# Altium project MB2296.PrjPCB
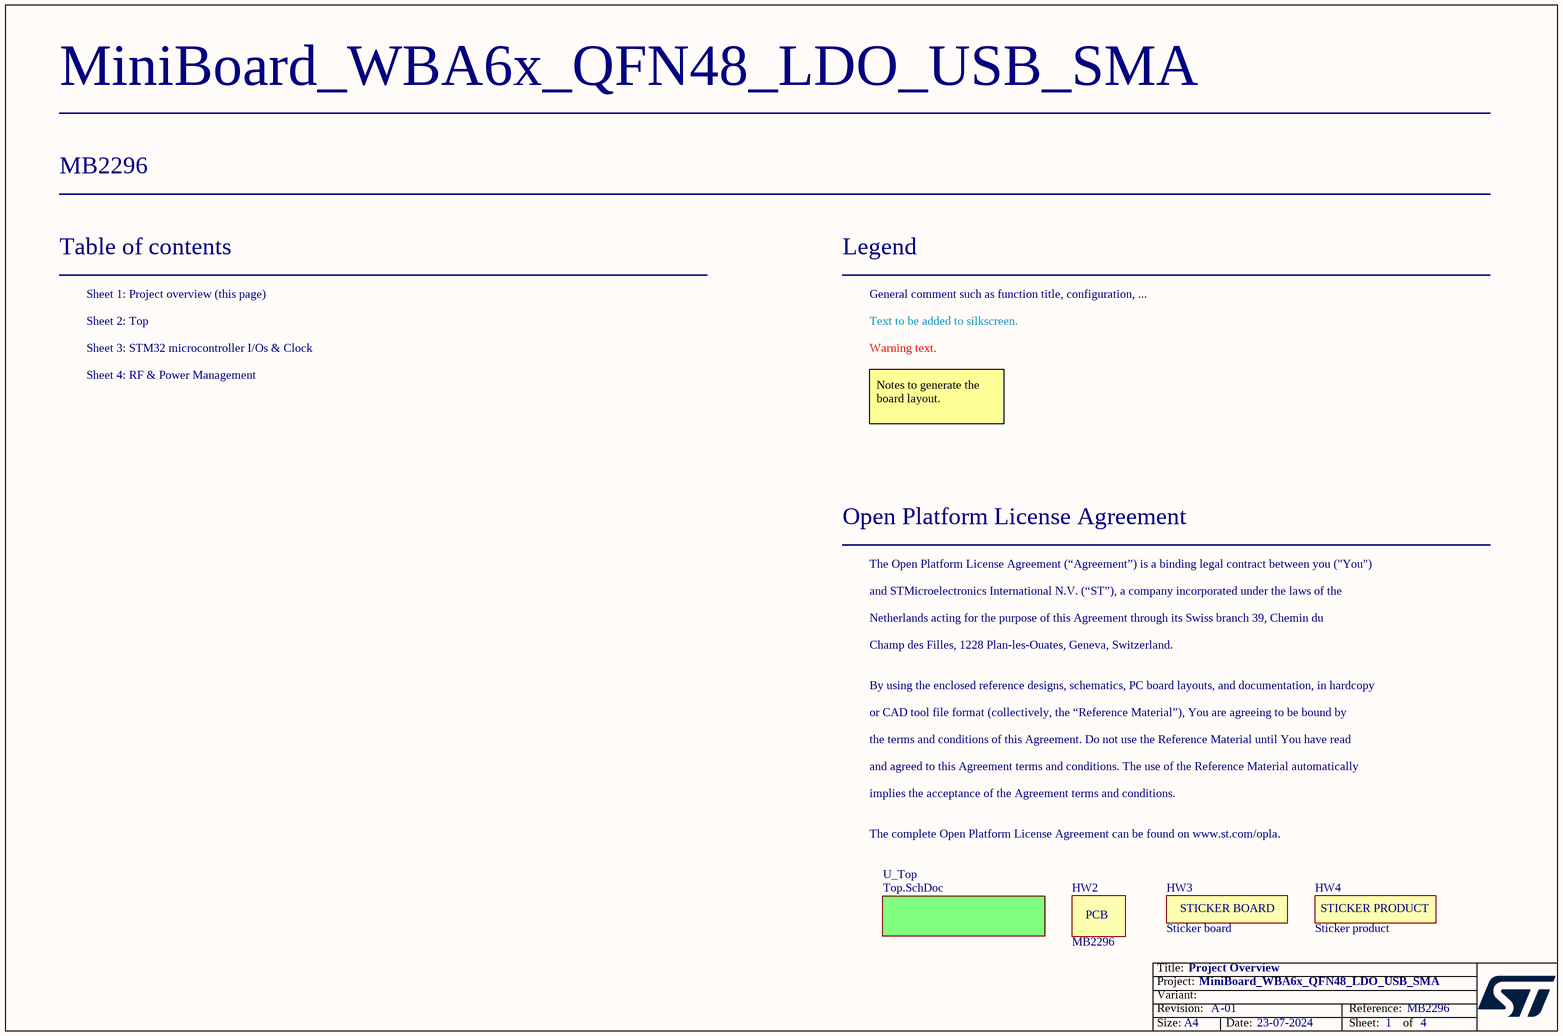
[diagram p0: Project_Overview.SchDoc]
Board_Assembly_Revision: 01; Board_Document_Date: 23-07-2024; Board_Name: MiniBoard_WBA6x_QFN48_LDO_USB_SMA; Board_PCB_Revision: A; Board_Reference: MB2296
4 sheets, 92 parts. Net scope: flat (ports and power ports of the same name join across sheets).
Board file: MB2296.PcbDoc
Sheets:
  Project_Overview.SchDoc
    U_Top = Top.SchDoc
      STM32 microcontroller I/Os & Clock = MCU.SchDoc
      RF & Power Management Schematic = RF&Power_Management.SchDoc

## Sheet Project_Overview.SchDoc: Project Overview
size A4; Date: Not used; ApprovedBy: Not used; CheckedBy: Not used; Author: Not used; CompanyName: STMicroelectronics; DrawnBy: Not used; Engineer: Not used; Organization: Not used; Address1: Not used; Address2: Not used; Address3: Not used; Address4: Not used; DocumentNumber: 1; Revision: Not used; SheetNumber: 1; SheetTotal: 4

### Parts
HW2  value MB2296  (hidden comment: PCB)  (no BOM)
HW3  value Sticker board  [STICKER_BOARD_25X5]  (hidden comment: STICKER_BOARD)  (no BOM)
HW4  value Sticker product  [STICKER_PRODUCT_25X5]  (hidden comment: STICKER_PRODUCT)  (no BOM)

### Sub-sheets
U_Top = Top.SchDoc: no entries

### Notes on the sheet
- Table of contents
- Sheet 1: Project overview (this page)
- Legend
- General comment such as function title, configuration, ...
- Sheet 2: Top
- Sheet 3: STM32 microcontroller I/Os & Clock
- Sheet 4: RF & Power Management
- Text to be added to silkscreen.
- Warning text.
- Notes to generate the board layout.
- Open Platform License Agreement
- The Open Platform License Agreement (“Agreement”) is a binding legal contract between you ("You")
- and STMicroelectronics International N.V. (“ST”), a company incorporated under the laws of the
- Netherlands acting for the purpose of this Agreement through its Swiss branch 39, Chemin du
- Champ des Filles, 1228 Plan-les-Ouates, Geneva, Switzerland.
- By using the enclosed reference designs, schematics, PC board layouts, and documentation, in hardcopy
- or CAD tool file format (collectively, the “Reference Material”), You are agreeing to be bound by
- the terms and conditions of this Agreement. Do not use the Reference Material until You have read
- and agreed to this Agreement terms and conditions. The use of the Reference Material automatically
- implies the acceptance of the Agreement terms and conditions.
- The complete Open Platform License Agreement can be found on www.st.com/opla.

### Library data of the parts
HW2 = MCD-03003: PCB MB1805, 4L2S of MiniBoard for STM32WBA55, QFN48, SMPS, SMA.; Part_Preference: Recommended; Manufacturer: PLOTEC; ShowFields: YES; ID: 5119
HW3 = MCD-02190: Sticker board 25x5 mm; Part_Type: Misc; Part_Preference: Recommended
HW4 = MCD-02189: Sticker product 25x5 mm; Part_Type: Misc; Part_Preference: Recommended

## Sheet Top.SchDoc: Top Schematic
size A4; Date: Not used; ApprovedBy: Not used; CheckedBy: Not used; Author: Not used; CompanyName: STMicroelectronics; DrawnBy: Not used; Engineer: Not used; Organization: Not used; Address1: Not used; Address2: Not used; Address3: Not used; Address4: Not used; DocumentNumber: 2; Revision: Not used; SheetNumber: 2; SheetTotal: 4
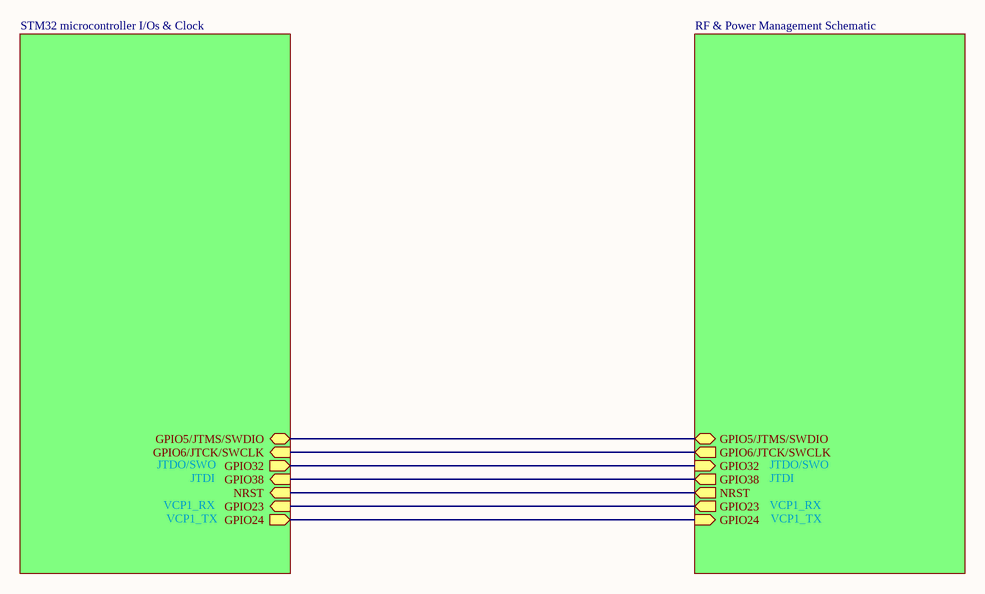
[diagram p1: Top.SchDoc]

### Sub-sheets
RF & Power Management Schematic = RF&Power_Management.SchDoc: GPIO5/JTMS/SWDIO (bidir), GPIO6/JTCK/SWCLK (out), GPIO32 (in), GPIO38 (out), NRST (out), GPIO23 (out), GPIO24 (in)
STM32 microcontroller I/Os & Clock = MCU.SchDoc: GPIO5/JTMS/SWDIO (bidir), GPIO6/JTCK/SWCLK (in), GPIO32 (out), GPIO38 (in), NRST (in), GPIO23 (in), GPIO24 (out)

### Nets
(unnamed): sheet STM32 microcontroller I/Os & Clock/GPIO5/JTMS/SWDIO, sheet RF & Power Management Schematic/GPIO5/JTMS/SWDIO
(unnamed): sheet STM32 microcontroller I/Os & Clock/GPIO6/JTCK/SWCLK, sheet RF & Power Management Schematic/GPIO6/JTCK/SWCLK  [a separate net that carries the same name]
(unnamed): sheet STM32 microcontroller I/Os & Clock/GPIO32, sheet RF & Power Management Schematic/GPIO32  [a separate net that carries the same name]
(unnamed): sheet STM32 microcontroller I/Os & Clock/GPIO38, sheet RF & Power Management Schematic/GPIO38  [a separate net that carries the same name]
(unnamed): sheet STM32 microcontroller I/Os & Clock/NRST, sheet RF & Power Management Schematic/NRST  [a separate net that carries the same name]
(unnamed): sheet STM32 microcontroller I/Os & Clock/GPIO23, sheet RF & Power Management Schematic/GPIO23  [a separate net that carries the same name]
(unnamed): sheet STM32 microcontroller I/Os & Clock/GPIO24, sheet RF & Power Management Schematic/GPIO24  [a separate net that carries the same name]

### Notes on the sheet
- JTDO/SWO
- VCP1_RX
- VCP1_TX
- JTDI

## Sheet MCU.SchDoc: STM32 microcontroller I/Os & Clock
size A4; Date: Not used; ApprovedBy: Not used; CheckedBy: Not used; Author: Not used; CompanyName: STMicroelectronics; DrawnBy: Not used; Engineer: Not used; Organization: Not used; Address1: Not used; Address2: Not used; Address3: Not used; Address4: Not used; DocumentNumber: 3; Revision: Not used; SheetNumber: 3; SheetTotal: 4
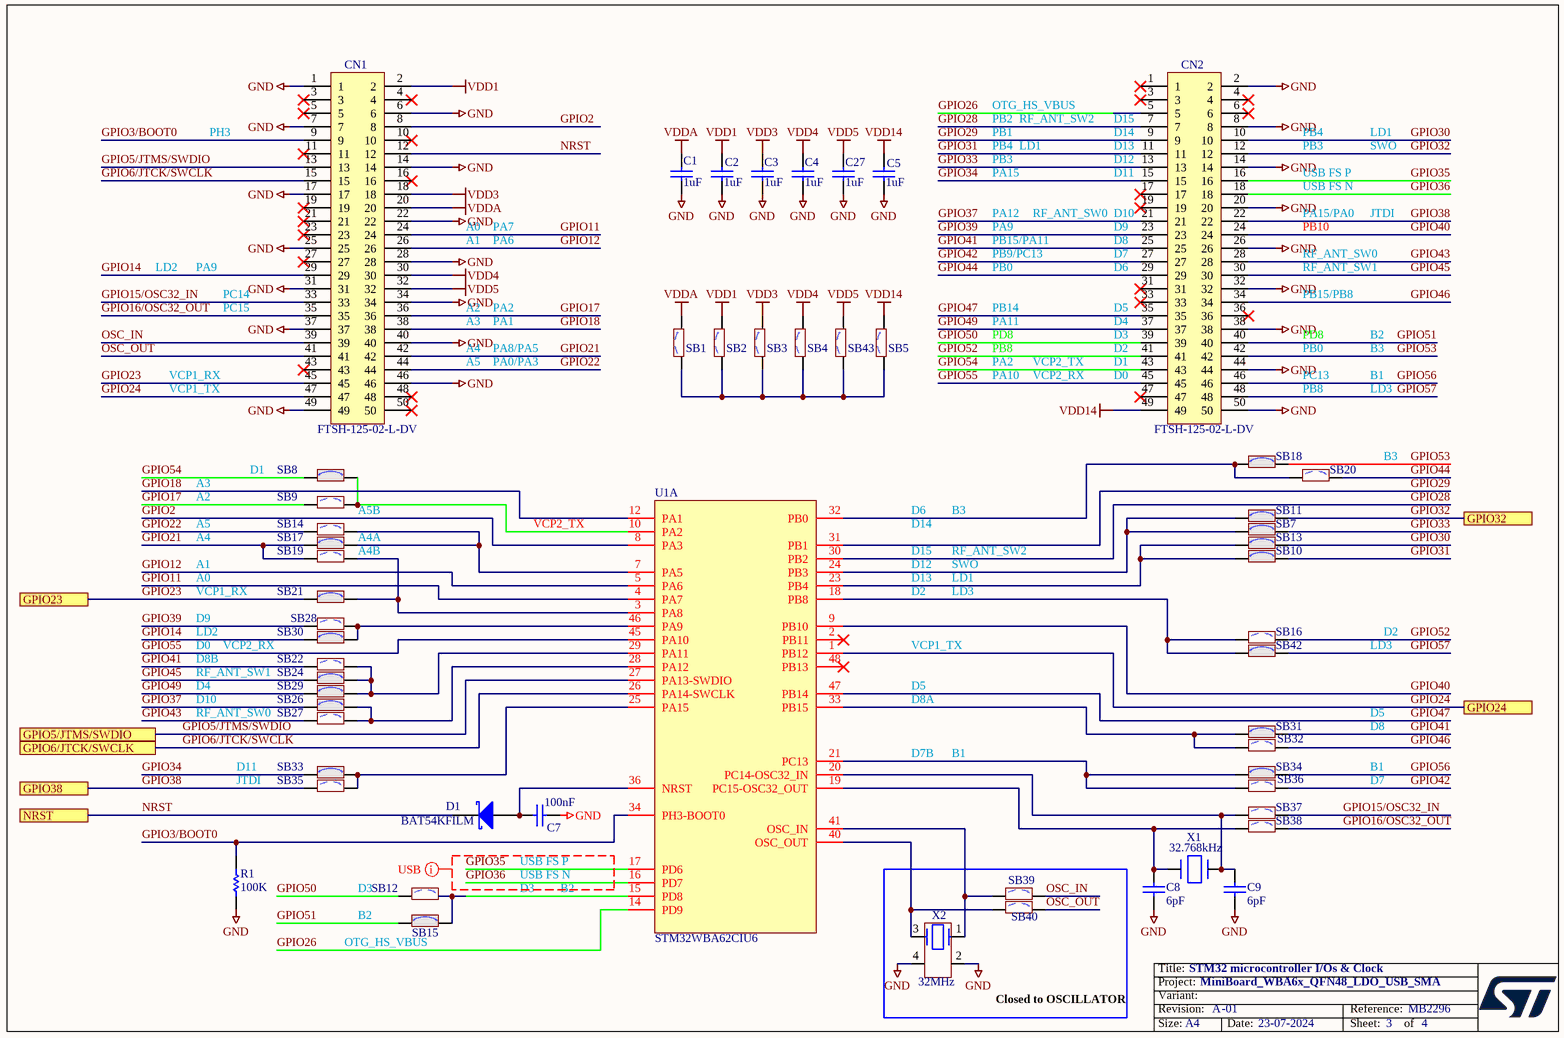
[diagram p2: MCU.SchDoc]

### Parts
C1  value 1uF  [C0402]  (hidden comment: Capacitor)
C2  value 1uF  [C0402]  (hidden comment: Capacitor)
C3  value 1uF  [C0402]  (hidden comment: Capacitor)
C4  value 1uF  [C0402]  (hidden comment: Capacitor)
C5  value 1uF  [C0402]  (hidden comment: Capacitor)
C7  value 100nF  [C0402]  (hidden comment: Capacitor)
C8  value 6pF  [C0402]  (hidden comment: Capacitor)
C9  value 6pF  [C0402]  (hidden comment: Capacitor)
C27  value 1uF  [C0402]  (hidden comment: Capacitor)
CN1  FTSH-125-02-L-DV  [CON_SAMTEC_FTSH-125-02-L-DV]
CN2  FTSH-125-02-L-DV  [CON_SAMTEC_FTSH-125-02-L-DV]
D1  value BAT54KFILM  [DIO_SOD523_1A_2K]  (hidden comment: SCHOTTKY_1A_2K)
R1  value 100K  [R0402]  (hidden comment: Resistor)
SB1  SB_OFF  [SOLDER-BRIDGE_R0402-0R]  (value not drawn)
SB2  SB_OFF  [SOLDER-BRIDGE_R0402-0R]  (value not drawn)
SB3  SB_OFF  [SOLDER-BRIDGE_R0402-0R]  (value not drawn)
SB4  SB_OFF  [SOLDER-BRIDGE_R0402-0R]  (value not drawn)
SB5  SB_OFF  [SOLDER-BRIDGE_R0402-0R]  (value not drawn)
SB7  SB_ON  [SOLDER-BRIDGE_R0402-0R]  (value not drawn)
SB8  SB_ON  [SOLDER-BRIDGE_R0402-0R]  (value not drawn)
SB9  SB_OFF  [SOLDER-BRIDGE_R0402-0R]  (value not drawn)
SB10  SB_ON  [SOLDER-BRIDGE_R0402-0R]  (value not drawn)
SB11  SB_ON  [SOLDER-BRIDGE_R0402-0R]  (value not drawn)
SB12  SB_OFF  [SOLDER-BRIDGE_R0402-0R]  (value not drawn)
SB13  SB_ON  [SOLDER-BRIDGE_R0402-0R]  (value not drawn)
SB14  SB_OFF  [SOLDER-BRIDGE_R0402-0R]  (value not drawn)
SB15  SB_ON  [SOLDER-BRIDGE_R0402-0R]  (value not drawn)
SB16  SB_OFF  [SOLDER-BRIDGE_R0402-0R]  (value not drawn)
SB17  SB_ON  [SOLDER-BRIDGE_R0402-0R]  (value not drawn)
SB18  SB_ON  [SOLDER-BRIDGE_R0402-0R]  (value not drawn)
SB19  SB_OFF  [SOLDER-BRIDGE_R0402-0R]  (value not drawn)
SB20  SB_OFF  [SOLDER-BRIDGE_R0402-0R]  (value not drawn)
SB21  SB_ON  [SOLDER-BRIDGE_R0402-0R]  (value not drawn)
SB22  SB_OFF  [SOLDER-BRIDGE_R0402-0R]  (value not drawn)
SB24  SB_ON  [SOLDER-BRIDGE_R0402-0R]  (value not drawn)
SB26  SB_ON  [SOLDER-BRIDGE_R0402-0R]  (value not drawn)
SB27  SB_OFF  [SOLDER-BRIDGE_R0402-0R]  (value not drawn)
SB28  SB_OFF  [SOLDER-BRIDGE_R0402-0R]  (value not drawn)
SB29  SB_ON  [SOLDER-BRIDGE_R0402-0R]  (value not drawn)
SB30  SB_ON  [SOLDER-BRIDGE_R0402-0R]  (value not drawn)
SB31  SB_ON  [SOLDER-BRIDGE_R0402-0R]  (value not drawn)
SB32  SB_OFF  [SOLDER-BRIDGE_R0402-0R]  (value not drawn)
SB33  SB_ON  [SOLDER-BRIDGE_R0402-0R]  (value not drawn)
SB34  SB_ON  [SOLDER-BRIDGE_R0402-0R]  (value not drawn)
SB35  SB_OFF  [SOLDER-BRIDGE_R0402-0R]  (value not drawn)
SB36  SB_OFF  [SOLDER-BRIDGE_R0402-0R]  (value not drawn)
SB37  SB_OFF  [SOLDER-BRIDGE_R0402-0R]  (value not drawn)
SB38  SB_OFF  [SOLDER-BRIDGE_R0402-0R]  (value not drawn)
SB39  SB_OFF  [SOLDER-BRIDGE_R0402-0R]  (value not drawn)
SB40  SB_OFF  [SOLDER-BRIDGE_R0402-0R]  (value not drawn)
SB42  SB_ON  [SOLDER-BRIDGE_R0402-0R]  (value not drawn)
SB43  SB_OFF  [SOLDER-BRIDGE_R0402-0R]  (value not drawn)
U1  STM32WBA62CIU6  [STM32WB62CGU6]  (part A of 3)
X1  value 32.768kHz  [CRY_NX1610SE_2P]  (hidden comment: XTAL_2_PINS)
X2  value 32MHz  [CRY_NX1612SA_4P]  (hidden comment: XTAL_4_PINS)

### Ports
GPIO5/JTMS/SWDIO, GPIO6/JTCK/SWCLK, GPIO23, GPIO24, GPIO32, GPIO38, NRST

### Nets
GND: C1.1 C2.1 C3.1 C4.1 C5.1 C7.1 C8.1 C9.1 C27.1 CN1.1 CN1.6 CN1.7 CN1.14 CN1.17 CN1.22 CN1.25 CN1.28 CN1.31 CN1.34 CN1.37 CN1.40 CN1.46 CN1.49 CN2.2 CN2.8 CN2.14 CN2.20 CN2.26 CN2.32 CN2.38 CN2.44 CN2.50 R1.2 X2.2 X2.4
VDD1: C2.2 CN1.2 SB2.2
VDD3: C3.2 CN1.18 SB3.2
VDD4: C4.2 CN1.30 SB4.2
VDD5: C27.2 CN1.32 SB43.2
VDD14: C5.2 CN2.49 SB5.2
VDDA: C1.2 CN1.20 SB1.2
GPIO2: CN1.8 U1.8(PA3)
GPIO3/BOOT0: CN1.9 R1.1 U1.34(PH3-BOOT0)
GPIO5/JTMS/SWDIO: CN1.13 U1.27(PA13-SWDIO) ; port GPIO5/JTMS/SWDIO
GPIO6/JTCK/SWCLK: CN1.15 U1.26(PA14-SWCLK) ; port GPIO6/JTCK/SWCLK
GPIO11: CN1.24 U1.4(PA7)
GPIO12: CN1.26 U1.5(PA6)
GPIO14: CN1.29 SB30.1
GPIO15/OSC32_IN: CN1.33 SB37.2
GPIO16/OSC32_OUT: CN1.35 SB38.2
GPIO17: CN1.36 SB9.1
GPIO18: CN1.38 U1.12(PA1)
GPIO21: CN1.42 SB17.1 SB19.1
GPIO22: CN1.44 SB14.1
GPIO23: CN1.45 SB21.1 ; port GPIO23
GPIO24: CN1.47 U1.1(PB12) ; port GPIO24
GPIO26: CN2.5 U1.14(PD9)
GPIO28: CN2.7 U1.30(PB2)
GPIO29: CN2.9 U1.31(PB1)
GPIO30: CN2.10 SB13.2
GPIO31: CN2.11 SB10.2
GPIO32: CN2.12 SB11.2 ; port GPIO32
GPIO33: CN2.13 SB7.2
GPIO34: CN2.15 SB33.1
GPIO35: CN2.16 U1.17(PD6)
GPIO36: CN2.18 U1.16(PD7)
GPIO37: CN2.21 SB26.1
GPIO38: CN2.22 SB35.1 ; port GPIO38
GPIO39: CN2.23 SB28.1
GPIO40: CN2.24 U1.9(PB10)
GPIO41: CN2.25 SB22.1 SB31.2
GPIO42: CN2.27 SB36.2
GPIO43: CN2.28 SB27.1
GPIO44: CN2.29 SB20.2
GPIO45: CN2.30 SB24.1
GPIO46: CN2.34 SB32.2
GPIO47: CN2.35 U1.47(PB14)
GPIO49: CN2.37 SB29.1
GPIO50: CN2.39 SB12.1
GPIO51: CN2.40 SB15.2
GPIO52: CN2.41 SB16.2
GPIO53: CN2.42 SB18.2
GPIO54: CN2.43 SB8.1
GPIO55: CN2.45 U1.45(PA10)
GPIO56: CN2.46 SB34.2
GPIO57: CN2.48 SB42.2
NRST: CN1.12 D1.2(K) ; port NRST
OSC_IN: CN1.39 SB39.2
OSC_OUT: CN1.41 SB40.2
NetC7_2: C7.2 D1.1(A) U1.36(NRST)
NetC8_2: C8.2 SB38.1 U1.19(PC15-OSC32_OUT) X1.2(X2)
NetC9_2: C9.2 SB37.1 U1.20(PC14-OSC32_IN) X1.1(X1)
NetSB1_1: SB1.1 SB2.1 SB3.1 SB4.1 SB5.1 SB43.1
NetSB7_1: SB7.1 SB11.1 U1.24(PB3)
NetSB8_2: SB8.2 SB9.2 U1.10(PA2)
NetSB10_1: SB10.1 SB13.1 U1.23(PB4)
NetSB12_2: SB12.2 SB15.1 U1.15(PD8)
NetSB14_2: SB14.2 SB17.2 U1.7(PA5)
NetSB16_1: SB16.1 SB42.1 U1.18(PB8)
NetSB18_1: SB18.1 SB20.1 U1.32(PB0)
NetSB19_2: SB19.2 SB21.2 U1.3(PA8)
NetSB22_2: SB22.2 SB24.2 SB29.2 U1.29(PA11)
NetSB26_2: SB26.2 SB27.2 U1.28(PA12)
NetSB28_2: SB28.2 SB30.2 U1.46(PA9)
NetSB31_1: SB31.1 SB32.1 U1.33(PB15)
NetSB33_2: SB33.2 SB35.2 U1.25(PA15)
NetSB34_1: SB34.1 SB36.1 U1.21(PC13)
NetSB39_1: SB39.1 U1.41(OSC_IN) X2.1
NetSB40_1: SB40.1 U1.40(OSC_OUT) X2.3

Not connected (* = marked no-connect by the designer): CN1 3* 4* 5* 10* 11* 16* 19* 21* 23* 27* 43* 48* 50*; CN2 1* 3* 4* 6* 17* 19* 31* 33* 36* 47*; U1 2(PB11)* 48(PB13)*

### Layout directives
rule Undefined; rule Matched Net Lengths [Tolerance = 2mm]; rule Impedance Constraint [Min = 85.00    Max = 95.00    ]: GPIO35, GPIO36

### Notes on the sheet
- OTG_HS_VBUS
- PH3
- PB1
- PB2
- PB3
- PB4
- PA15
- LD1
- RF_ANT_SW2
- (near CN2) D11
- (near CN2) D13
- (near CN2) D14
- (near CN2) D15
- (near CN2) D12
- USB FS P
- SWO
- A0
- A1
- PA6
- PA7
- PA9
- PB15/PA11
- PA12
- RF_ANT_SW0
- (near CN2) D10
- (near CN2) D9
- (near CN2) D8
- PA15/PA0
- PB10
- USB FS N
- JTDI
- LD2
- PC14
- PC15
- A2
- PA2
- PB14
- PB0
- PB9/PC13
- (near CN2) D7
- (near CN2) D6
- (near CN2) D5
- RF_ANT_SW1
- PB15/PB8
- VCP1_RX
- A5
- A4
- A3
- PA0/PA3
- PA8/PA5
- PA1
- PA11
- PA10
- PD8
- PB8
- VCP2_TX
- VCP2_RX
- (near CN2) D1
- (near CN2) D4
- (near CN2) D3
- (near CN2) D2
- (near CN2) D0
- PC13
- B1
- B2
- B3
- VCP1_TX
- LD3
- D1
- A5B
- D6
- A4B
- A4A
- D12
- D13
- D15
- D14
- D0
- D9
- D2
- D10
- D8B
- D4
- D8A
- D5
- D11
- D7B
- D7
- D8
- D3
- (near SB15) OTG_HS_VBUS
- Closed to OSCILLATOR

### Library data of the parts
C1-C5 C27 = MCD-01722: Capacitor, MLCC, 1uF, 10V, X5R, +/-10%, 0402, T=0.5mm; Part_Preference: Recommended; Manufacturer: YAGEO; Manufacturer_Part_Number: CC0402KRX5R6BB105; Component_Country_Of_Origin: China
C7 = MCD-00006: Capacitor, MLCC, 100nF, 16V, X7R, +/-10%, 0402, T=0.5mm; Manufacturer_Part_Number: CC0402KRX7R7BB104; Manufacturer: YAGEO; Alternate_Manufacturer_Part_Number: GCM155R71C104KA55D; Alternate_Manufacturer: MURATA; Part_Preference: Recommended; Order_Code_RS: 616-9701
C8 C9 = MCD-03185: Capacitor, MLCC, 6 pF, 50V, NPO, ±0,25pF, 0402, T=0.5mm; Part_Preference: Recommended; Manufacturer: MURATA; Manufacturer_Part_Number: GJM1555C1H6R0CB01; Order_Code_RS: 170-6040; ShowFields: YES; ID: 5301
CN1 CN2 = MCD-02746: Header, 25x2, 12.7mm, VR, SMD, T=4.83mm; Part_Type: Connector; Part_Preference: Recommended; Manufacturer: SAMTEC; Value: Header 25x2; ShowFields: YES; ID: 4858; Component_Country_Of_Origin: China, Costa Rica, Malaysia, USA, Vietnam
D1 = MCD-01677: Small signal Schottky diodes; Part_Type: Diode; Manufacturer: STMICROELECTRONICS; BMS_Part_Number: 9151123; Part_Preference: Recommended; Manufacturer_HQ_COO: EU
R1 = MCD-00059: Resistor, 100K, 0402, +/-1%, 1/16W; Part_Preference: Recommended; Manufacturer: YAGEO; Manufacturer_Part_Number: RC0402FR-07100KL; Component_Country_Of_Origin: China
SB1-SB5 SB9 SB12 SB14 SB16 SB19 SB20 SB22 SB27 SB28 SB32 SB35-SB40 SB43 = MCD-02162: Solder Bridge 0402 OFF; Part_Type: Misc; Part_Preference: Recommended; Manufacturer: YAGEO; Manufacturer_Part_Number: RC0402JR-070RL; Order_Code_RS: 618-5804; Component_Country_Of_Origin: China
SB7 SB8 SB10 SB11 SB13 SB15 SB17 SB18 SB21 SB24 SB26 SB29-SB31 SB33 SB34 SB42 = MCD-01618: Solder Bridge 0402 ON; Part_Type: Misc; Part_Preference: Recommended; Manufacturer: YAGEO; Manufacturer_Part_Number: RC0402JR-070RL; Order_Code_RS: 618-5804; Component_Country_Of_Origin: China
U1 = STM32WBA62CIU6: STM32WBA62CIU6 QFN48_USB_LDO; Internal_Part_Number: MCD-04241; Manufacturer: STmicroelectronics; ECCN_EU: NEC°°°; ECCN_US: EAR99°°°
X1 = MCD-02579: Crystal, 32.768kHz, 6pF, +/-20ppm, 70KR, 1.6x1mm; Part_Type: Crystal_Osc; Part_Preference: Recommended; Manufacturer: NDK; Manufacturer_Part_Number: NX1610SE-32.768KHZ-EXS00A-MU01501
X2 = MCD-02578: Crystal, 32MHz, 8pF, +/-10ppm, 40R, 1612(metric), T=0.3mm; Part_Type: Crystal_Osc; Part_Preference: Recommended; Manufacturer: NDK; Manufacturer_Part_Number: NX1612SA-32MHZ-EXS00A-CS09166

## Sheet RF&Power_Management.SchDoc: RF & Power Management Schematic
size A4; Date: Not used; ApprovedBy: Not used; CheckedBy: Not used; Author: Not used; CompanyName: STMicroelectronics; DrawnBy: Not used; Engineer: Not used; Organization: Not used; Address1: Not used; Address2: Not used; Address3: Not used; Address4: Not used; DocumentNumber: 4; Revision: Not used; SheetNumber: 4; SheetTotal: 4
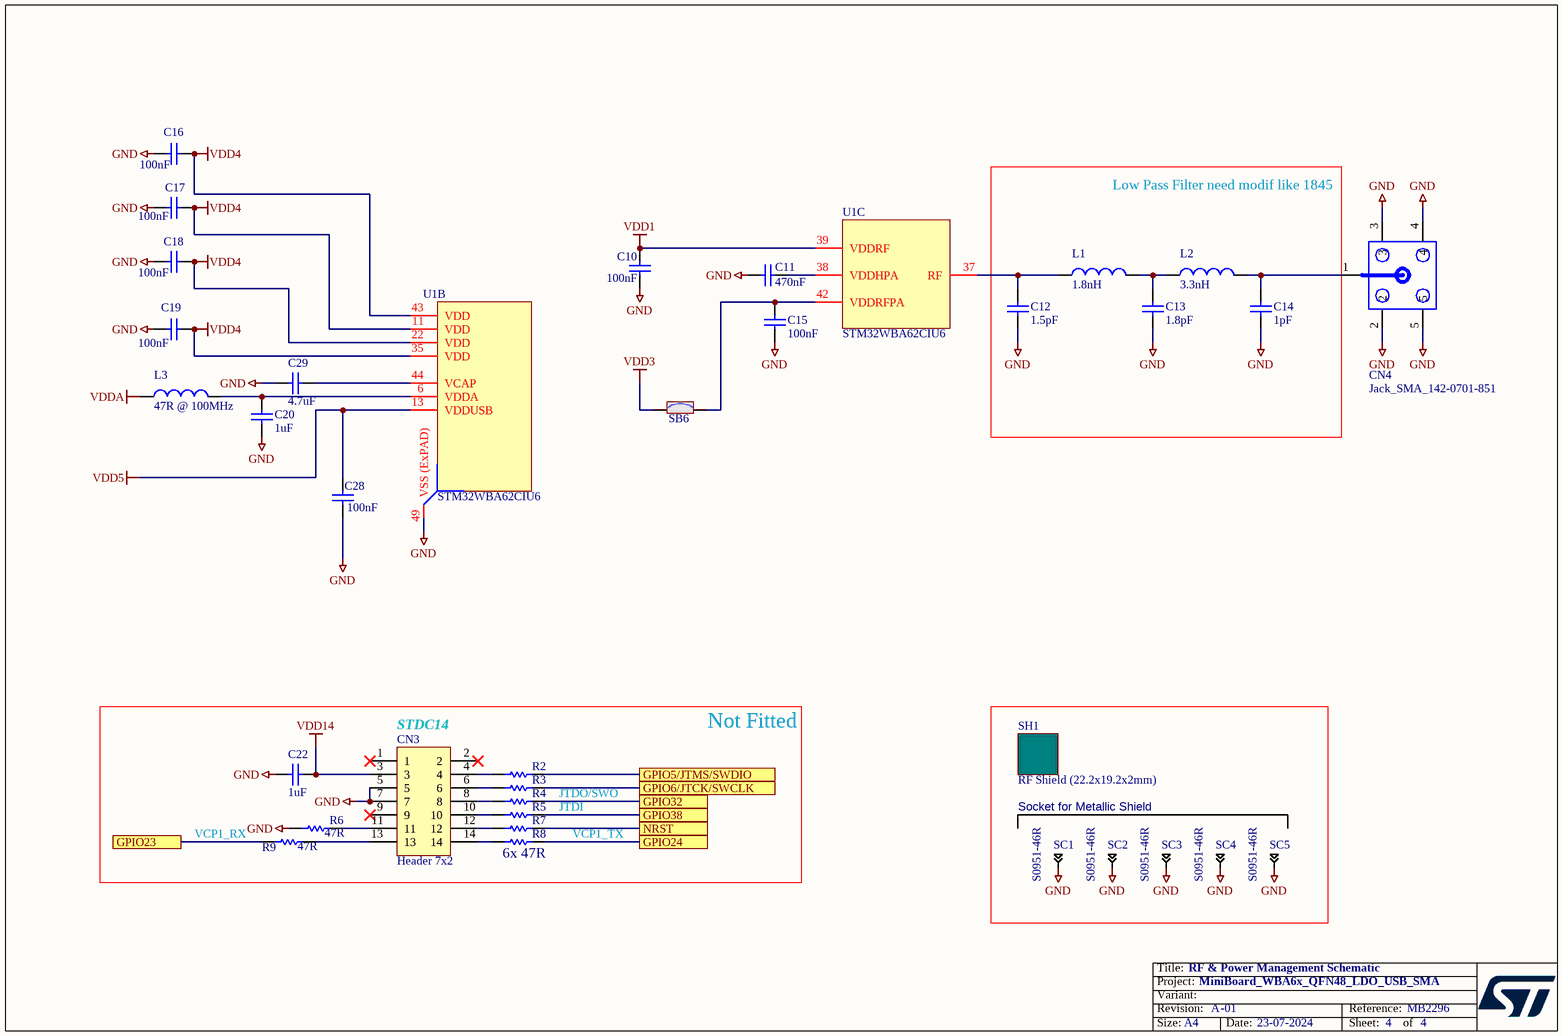
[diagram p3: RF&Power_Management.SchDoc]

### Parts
C10  value 100nF  [C0402]  (hidden comment: Capacitor)
C11  value 470nF  [C0603]  (hidden comment: Capacitor)
C12  value 1.5pF  [C0402]  (hidden comment: Capacitor)
C13  value 1.8pF  [C0402]  (hidden comment: Capacitor)
C14  value 1pF  [C0402_MURATA_GRM155_H0P5]  (hidden comment: Capacitor)
C15  value 100nF  [C0402]  (hidden comment: Capacitor)
C16  value 100nF  [C0402]  (hidden comment: Capacitor)
C17  value 100nF  [C0402]  (hidden comment: Capacitor)
C18  value 100nF  [C0402]  (hidden comment: Capacitor)
C19  value 100nF  [C0402]  (hidden comment: Capacitor)
C20  value 1uF  [C0402]  (hidden comment: Capacitor)
C22  value 1uF  [C0603]  (hidden comment: Capacitor)
C28  value 100nF  [C0402]  (hidden comment: Capacitor)
C29  value 4.7uF  [C0603_H0P8]  (hidden comment: Capacitor)
CN3  Header 7x2  [CON_SAMTEC_FTSH-107-01-L-DV-K-A]
CN4  value Jack_SMA_142-0701-851  [CON_SMA-RF_CINCH_142-0701-851]  (hidden comment: mmcx)
L1  value 1.8nH  [C0402]  (hidden comment: Inductor)
L2  value 3.3nH  [C0402]  (hidden comment: Inductor)
L3  value 47R @ 100MHz  [IND_0603_H0P8]  (hidden comment: Inductor)
R2  Resistor  [R0402]  (value not drawn)
R3  Resistor  [R0402]  (value not drawn)
R4  Resistor  [R0402]  (value not drawn)
R5  Resistor  [R0402]  (value not drawn)
R6  value 47R  [R0402]  (hidden comment: Resistor)
R7  Resistor  [R0402]  (value not drawn)
R8  Resistor  [R0402]  (value not drawn)
R9  value 47R  [R0402]  (hidden comment: Resistor)
SB6  SB_ON  [SOLDER-BRIDGE_R0402-0R]  (value not drawn)
SC1  value S0951-46R  [CLIP_HARWIN_S0951-46R]  (hidden comment: Shield-clip_S0951-46R)
SC2  value S0951-46R  [CLIP_HARWIN_S0951-46R]  (hidden comment: Shield-clip_S0951-46R)
SC3  value S0951-46R  [CLIP_HARWIN_S0951-46R]  (hidden comment: Shield-clip_S0951-46R)
SC4  value S0951-46R  [CLIP_HARWIN_S0951-46R]  (hidden comment: Shield-clip_S0951-46R)
SC5  value S0951-46R  [CLIP_HARWIN_S0951-46R]  (hidden comment: Shield-clip_S0951-46R)
SH1  RF Shield (22.2x19.2x2mm)  [SHIELD_RF_ST-CUSTOM_22P2X19P2_H2]
U1  STM32WBA62CIU6  [STM32WB62CGU6]  (parts B,C of 3)

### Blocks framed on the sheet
Low Pass Filter need modif like 1845: C12-C14 L1 L2
Not Fitted: C22 CN3 R2-R9
Socket for Metallic Shield: SC1-SC5 SH1

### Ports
GPIO5/JTMS/SWDIO, GPIO6/JTCK/SWCLK, GPIO23, GPIO24, GPIO32, GPIO38, NRST

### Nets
GND: C10.2 C11.1 C12.1 C13.1 C14.1 C15.2 C16.2 C17.2 C18.2 C19.2 C20.1 C22.1 C28.2 C29.2 CN3.5 CN3.7 CN4.2 CN4.3 CN4.4 CN4.5 R6.1 SC1.1 SC2.1 SC3.1 SC4.1 SC5.1 U1.49(VSS_(ExPAD))
VDD1: C10.1 U1.39(VDDRF)
VDD3: SB6.1
VDD4: C16.1 C17.1 C18.1 C19.1 U1.11(VDD) U1.22(VDD) U1.35(VDD) U1.43(VDD)
VDD5: C28.1 U1.13(VDDUSB)
VDD14: C22.2 CN3.3
VDDA: L3.1
GPIO5/JTMS/SWDIO: R2.2 ; port GPIO5/JTMS/SWDIO
GPIO6/JTCK/SWCLK: R3.2 ; port GPIO6/JTCK/SWCLK
GPIO23: R9.1 ; port GPIO23
GPIO24: R8.2 ; port GPIO24
GPIO32: R4.2 ; port GPIO32
GPIO38: R5.2 ; port GPIO38
NRST: R7.2 ; port NRST
NetC11_2: C11.2 U1.38(VDDHPA)
NetC12_2: C12.2 L1.1 U1.37(RF)
NetC13_2: C13.2 L1.2 L2.1
NetC14_2: C14.2 CN4.1 L2.2
NetC15_1: C15.1 SB6.2 U1.42(VDDRFPA)
NetC20_2: C20.2 L3.2 U1.6(VDDA)
NetC29_1: C29.1 U1.44(VCAP)
NetCN3_4: CN3.4 R2.1
NetCN3_6: CN3.6 R3.1
NetCN3_8: CN3.8 R4.1
NetCN3_10: CN3.10 R5.1
NetCN3_11: CN3.11 R6.2
NetCN3_12: CN3.12 R7.1
NetCN3_13: CN3.13 R9.2
NetCN3_14: CN3.14 R8.1

Not connected (* = marked no-connect by the designer): CN3 1* 2* 9*

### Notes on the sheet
- (near CN3) STDC14
- (near R9) VCP1_RX
- JTDI
- JTDO/SWO
- VCP1_TX
- (near R8) 6x 47R

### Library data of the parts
C10 C15-C19 C28 = MCD-00006: as C7 on sheet MCU
C11 = MCD-01006: Capacitor, MLCC, 470nF, 16V, X7R, +/-10%, 0603, T=0.8mm; BMS_Part_Number: 9142003; Part_Preference: Recommended; Manufacturer: YAGEO; Manufacturer_Part_Number: CC0603KRX7R7BB474; Order_Code_RS: 200-6576; Component_Country_Of_Origin: China
C12 = MCD-02994: Capacitor, MLCC, 1.5pF, 50V, C0G, +/-0.25pF, 0402, T=0.5mm; Part_Preference: Recommended; Manufacturer: MURATA; Manufacturer_Part_Number: GRM1555C1H1R5CA01; Component_Country_Of_Origin: Japan°; ShowFields: YES; ID: 5110
C13 = MCD-02995: Capacitor, MLCC, 1.8pF, 50V, C0G, +/-0.25pF, 0402, T=0.5mm; Part_Preference: Recommended; Manufacturer: MURATA; Manufacturer_Part_Number: GRM1555C1H1R8CA01; Order_Code_RS: 723-5357; Component_Country_Of_Origin: Japan°; ShowFields: YES; ID: 5111
C14 = MCD-03737: Capacitor, MLCC, 1pF, 50V, C0G, +/-0.1pF, 0402, T=0.5mm; Part_Preference: Recommended; Manufacturer: MURATA; Manufacturer_Part_Number: GJM1555C1H1R0BB01D; Order_Code_RS: 185-3145; Component_Country_Of_Origin: Japan, Singapore; ShowFields: YES; ID: 5853
C20 = MCD-01722: as C1 on sheet MCU
C22 = MCD-00010: Capacitor, MLCC, 1uF, 16V, X5R, 10%, 0603, T=0,8mm; Manufacturer_Part_Number: CC0603KRX5R7BB105; Manufacturer: YAGEO; Provided_By: Subcon; Initial_Board_Reference: MB1274
C29 = MCD-01721: Capacitor, MLCC, 4.7uF, 10V, X5R, +/-10%, 0603, T=0.8mm; Part_Preference: Recommended; Manufacturer: YAGEO; Manufacturer_Part_Number: CC0603KRX5R6BB475; Component_Country_Of_Origin: China
CN3 = MCD-01531: Header, 7x2, 1.27mm, VR, T=5.97mm, FTSH series STDC14 without Alignment Pin; Part_Type: Connector; Part_Preference: Recommended; Manufacturer: SAMTEC; Manufacturer_Part_Number: FTSH-107-01-L-DV-K; Order_Code_RS: 179-9021; Component_Country_Of_Origin: China, Costa Rica, Malaysia, United States, Vietnam
CN4 = MCD-02072: Jack_SMA, VR, PCB edge, 50R, T=7.92mm; Part_Type: Connector; Part_Preference: Recommended; Manufacturer: CINCH; Manufacturer_Part_Number: 142-0701-851; Order_Code_RS: 885-7532; Component_Country_Of_Origin: United States; ShowFields: YES; ID: 4172
L1 = MCD-02998: Inductor, 1.8nH, +/-0.3nH, 0.95A, 80mR, 0402, T=0.5mm; Part_Preference: Recommended; Manufacturer: MURATA; Manufacturer_Part_Number: LQG15HS1N8S02; Component_Country_Of_Origin: Japan°; ShowFields: YES; ID: 5114
L2 = MCD-03001: Inductor, 3.3nH, +/-0.3nH, 0.8A,125mR, 0402, T=0.5mm; Part_Preference: Recommended; Manufacturer: MURATA; Manufacturer_Part_Number: LQG15HS3N3S02; Component_Country_Of_Origin: Japan°; ShowFields: YES; ID: 5117
L3 = MCD-03831: Ferrite bead, 47R @ 100MHz, +/-25%, 3.5A, 0R02, 0603, T=0.8mm; Part_Preference: Recommended; Manufacturer: TAIYO YUDEN; Manufacturer_Part_Number: LSMGA160808T470RG; ShowFields: YES; ID: 5947
R2-R9 = MCD-00481: Resistor,47R,0402,1%,1/16W; Manufacturer_Part_Number: RC0402FR-0747RL; Manufacturer: YAGEO; Provided_By: Subcon
SB6 = MCD-01618: as SB7 on sheet MCU
SC1-SC5 = MCD-01587: shield clip Harwin S0951-46R to fix RF shielded cavity; Part_Type: Misc; Part_Preference: Recommended; Component_Country_Of_Origin: South Korea
SH1 = MCD-03256: Part_Type: Misc; Part_Preference: Recommended; Manufacturer: TBD; ShowFields: YES; ID: 5372
U1 = STM32WBA62CIU6: as U1 on sheet MCU

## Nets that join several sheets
GND: MCU (35 pins), RF&Power_Management (27 pins)
VDD1: MCU (C2.2 CN1.2 SB2.2), RF&Power_Management (C10.1 U1.39)
VDD3: MCU (C3.2 CN1.18 SB3.2), RF&Power_Management (SB6.1)
VDD4: MCU (C4.2 CN1.30 SB4.2), RF&Power_Management (8 pins)
VDD5: MCU (C27.2 CN1.32 SB43.2), RF&Power_Management (C28.1 U1.13)
VDD14: MCU (C5.2 CN2.49 SB5.2), RF&Power_Management (C22.2 CN3.3)
VDDA: MCU (C1.2 CN1.20 SB1.2), RF&Power_Management (L3.1)
GPIO5/JTMS/SWDIO: MCU (CN1.13 U1.27), RF&Power_Management (R2.2)
GPIO6/JTCK/SWCLK: MCU (CN1.15 U1.26), RF&Power_Management (R3.2)
GPIO23: MCU (CN1.45 SB21.1), RF&Power_Management (R9.1)
GPIO24: MCU (CN1.47 U1.1), RF&Power_Management (R8.2)
GPIO32: MCU (CN2.12 SB11.2), RF&Power_Management (R4.2)
GPIO38: MCU (CN2.22 SB35.1), RF&Power_Management (R5.2)
NRST: MCU (CN1.12 D1.2), RF&Power_Management (R7.2)

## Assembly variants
WBA62CIU: not fitted C1 C2 C3 C4 C5 C22 C27 CN3 R2 R3 R4 R5 R6 R7 R8 R9 SB1 SB2 SB3 SB4 SB5 SB9 SB12 SB14 SB16 SB19 SB20 SB22 SB27 SB28 SB32 SB35 SB36 SB37 SB38 SB39 SB40 SB43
